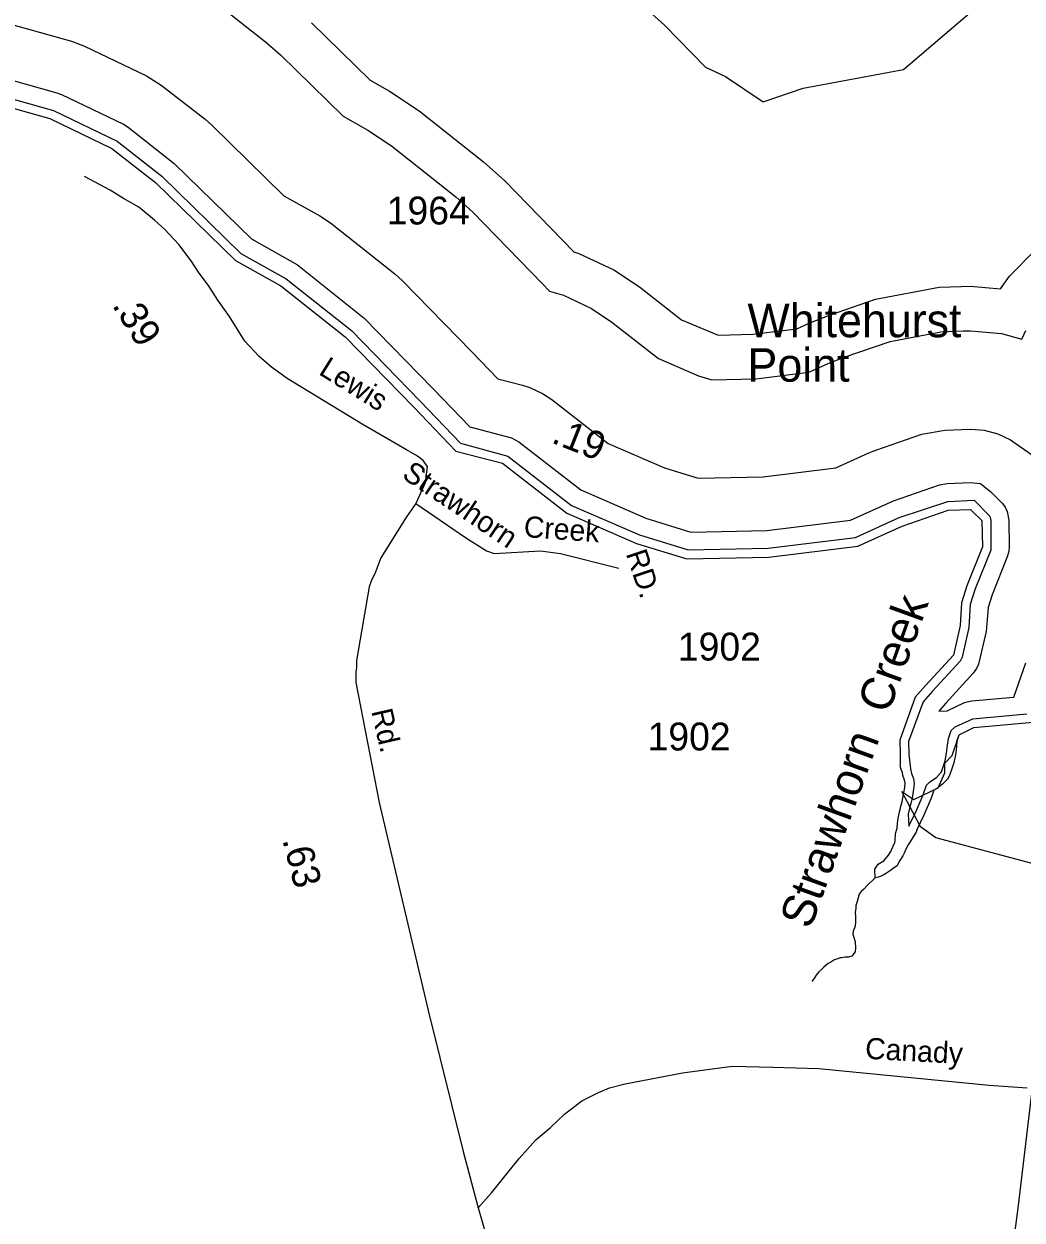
# Model space of a CAD drawing. Extents: x 2532689 to 2764727, y 536648 to 732970.
# Drawn here: x 2695958 to 2700431, y 583950 to 589311 of the extents above; entities that cross this region are included whole.
import ezdxf

# ---------------------------------------------------------------- set-up
doc = ezdxf.new("R2010")
doc.units = 0
for name, color, linetype in [('Exist Boundary Land Use Gamelands State NC Wildlife Resources Commission', 7, 'Continuous'), ('Exist Hydrographic Buffer Line', 7, 'Continuous'), ('Exist Hydrographic Creek Double Shore', 7, 'Continuous'), ('Exist Hydrographic Creek Single Shore', 7, 'Continuous'), ('Exist Hydrographic Creek Single Shore Label', 7, 'Continuous'), ('Exist Hydrographic Point Label', 7, 'Continuous'), ('Exist Hydrographic River Shore', 7, 'Continuous'), ('Exist Road Secondary Mileage Hundredths English Label', 7, 'Continuous'), ('Exist Road Secondary Type 41 Attributed', 7, 'Continuous'), ('Exist Road Secondary Type 51 Attributed', 7, 'Continuous'), ('Exist Road Secondary Type 51 Label', 7, 'Continuous'), ('Exist Road Secondary Type 51 Number Label', 7, 'Continuous')]:
    doc.layers.add(name, color=color, linetype=linetype)

msp = doc.modelspace()

# ---------------------------------------------------------------- linework, layer by layer
at = {"layer": 'Exist Boundary Land Use Gamelands State NC Wildlife Resources Commission'}
for points in [[(2700588.2, 585518), (2700044.4, 585663.1), (2699975.9, 585712.3), (2699941.3, 585777.8), (2699892.3, 585871.1), (2699946.2, 585834.2), (2700054.3, 585887.7), (2700085.2, 585954.7), (2700084.2, 585997.3), (2700117.2, 586031.5), (2700148.2, 586124.7), (2700214.2, 586156.9), (2700480.2, 586180.8)], [(2700290.5, 583072.7), (2700414.8, 584014.9), (2700500.1, 584730.4)]]:
    msp.add_lwpolyline(points, dxfattribs=at)
at = {"layer": 'Exist Hydrographic Buffer Line'}
for points in [[(2698638.4, 589476.4), (2698828.9, 589304.6), (2699012.4, 589116.4), (2699102, 589074.7), (2699270.8, 588961.2), (2699449.2, 589022.6), (2699898.6, 589107), (2700237.2, 589395)], [(2696844.2, 589383.5), (2697040.2, 589230.5), (2697107.3, 589171.9), (2697389, 588896.5), (2697498.9, 588835.1), (2697605.7, 588763.7), (2697893.6, 588535.7), (2697969.7, 588466.9), (2698282.2, 588146.3), (2698313.8, 588113.6), (2698375.5, 588094.3), (2698502, 588035.4), (2698593.1, 587974.1), (2698802, 587811.6), (2698980.6, 587734.2), (2699040.7, 587715.7), (2699238.2, 587720.2), (2699475.6, 587749.2), (2699561.7, 587788.4), (2699633.3, 587816.9), (2699839.2, 587887.6), (2700066.4, 587930.3), (2700166.4, 587934.4), (2700199, 587935), (2700337.9, 587922.9), (2700429.1, 587898.3), (2700447.4, 587937.3)], [(2695894, 589310.4), (2696171, 589232.8), (2696229.4, 589210.8)], [(2697246.9, 589315), (2697509.8, 589058.1), (2697596.5, 589009.8), (2697729.8, 588920.5), (2698017.7, 588692.4), (2698113, 588606.6), (2698422.7, 588288.9), (2698444, 588282.3), (2698601.9, 588208.6), (2698715.9, 588132), (2698904.7, 587985.1), (2699068.8, 587916.4), (2699223.8, 587919.8), (2699420.7, 587944), (2699478.9, 587970.4), (2699568.3, 588006), (2699774.2, 588076.7), (2700058.4, 588130.1), (2700158.4, 588134.2), (2700199, 588135), (2700334.4, 588123.2), (2700374.2, 588180.1), (2700492.3, 588298.9)], [(2696229.4, 589210.8), (2696507.5, 589077.5), (2696573.5, 589036.7), (2696769.5, 588883.6), (2696799.7, 588857.3), (2697123.3, 588540.8), (2697284.4, 588450.9), (2697332.4, 588418.8), (2697620.5, 588190.8), (2697654.8, 588159.8), (2697964.8, 587841.7), (2698082.1, 587719.6), (2698192, 587691.2), (2698225.2, 587680.9), (2698282, 587654.4), (2698323, 587626.8), (2698576, 587430), (2698828.1, 587320.8), (2698979.2, 587274.2), (2699269.9, 587280.7), (2699596.2, 587320.7), (2699744, 587387.9), (2699776, 587400.7), (2699981.9, 587471.5), (2700084.4, 587490.6), (2700199, 587495), (2700261.4, 587489.5), (2700322.3, 587473.3), (2700378.9, 587446.7), (2700488.3, 587370.5)], [(2695829.2, 589079.2), (2696106.2, 589001.7), (2696125.7, 588994.3), (2696403.7, 588861.1), (2696425.7, 588847.5), (2696632, 588685.7), (2696978.5, 588346.9), (2697183.5, 588230.7), (2697482.9, 587992.2), (2697791.5, 587675.6), (2697956, 587504.3), (2698143, 587455.4), (2698175.8, 587437.4), (2698452.8, 587221.9), (2698744.8, 587095.4), (2698945.8, 587033.4), (2699287.2, 587041), (2699662, 587087), (2699853.9, 587173.7), (2700060, 587244.5), (2700094.3, 587250.8), (2700199, 587255), (2700243.8, 587251.1)], [(2695807.6, 589002.2), (2696091.2, 588922.2), (2696376.5, 588784.4), (2696576, 588628.5), (2696930.3, 588282.2), (2697133.7, 588168), (2697425.7, 587936.5), (2697733.7, 587620.3), (2697913.9, 587432.4), (2698126.6, 587374.2)], [(2698126.6, 587374.2), (2698411.4, 587152.5), (2698716.9, 587020.2), (2698934.5, 586953.2), (2699292.9, 586961.1), (2699683.9, 587009.1), (2699880, 587098), (2700097.5, 587170.9), (2700215.5, 587175.7)], [(2700243.8, 587251.1), (2700290.7, 587213.3), (2700343, 587161.6), (2700354.9, 587144.5), (2700363.7, 587125.6), (2700370.9, 587086.6), (2700372.9, 586966.5), (2700371.3, 586945.6), (2700364.3, 586921.6), (2700296, 586752.3), (2700278, 586694.6), (2700270, 586587.8), (2700235.7, 586440.7), (2700226.9, 586421.7), (2700211.8, 586401), (2700088.9, 586265.9), (2700056.9, 586230.9), (2700095.7, 586232.6), (2700173.2, 586269.6)], [(2700215.5, 587175.7), (2700285.8, 587104.5), (2700290.9, 587085.2), (2700289.9, 586951.5), (2700220.8, 586779.3), (2700198.6, 586709.1), (2700192.1, 586605.5), (2700161.9, 586472.9), (2700152.5, 586454.8), (2700029.7, 586319.8), (2699987.2, 586273.1), (2699922.4, 586094.3), (2699923.7, 586038.2), (2699931.4, 585972.5), (2699935.3, 585951.1), (2699943.7, 585928.6), (2699946.4, 585905.8), (2699944.8, 585881.9), (2699937.4, 585841.4), (2699932.7, 585816.8), (2699926.7, 585795.6), (2699919.6, 585768.9), (2699923.7, 585715.2), (2699956.1, 585782), (2699987, 585856.4), (2700001.8, 585898.9), (2700017.8, 585914.1), (2700047.3, 585933.5), (2700069.4, 585958.8), (2700085.4, 586008.6), (2700092, 586042.3), (2700096.5, 586077.6), (2700100.4, 586108.5), (2700113.5, 586144.7), (2700130.8, 586160.6), (2700210.7, 586196.7), (2700451.3, 586218.3)], [(2700173.2, 586269.6), (2700203.5, 586276.4), (2700393.2, 586293.4), (2700447.6, 586447.9)]]:
    msp.add_lwpolyline(points, dxfattribs=at)
at = {"layer": 'Exist Hydrographic Creek Double Shore'}
for p, q in [((2699883.7, 586037.5), (2699884.7, 585985.7)), ((2700036.4, 585878.9), (2700054.5, 585888.5))]:
    msp.add_line(p, q, dxfattribs=at)
for points in [[(2700207, 587127.3), (2700250.9, 587084.5), (2700253, 586966.5), (2700183, 586792.8), (2700159.1, 586716.4), (2700152.9, 586614.3), (2700123, 586481.8), (2700000.1, 586346.7)], [(2700138.5, 586095.8), (2700148.2, 586124.7), (2700214.2, 586156.9), (2700480.2, 586180.8), (2700504.2, 586247.4), (2700566.3, 586423.9), (2700578.2, 586624.7), (2700634.2, 586719), (2701022.5, 586817.8)], [(2700000.1, 586346.7), (2699952.2, 586294.1), (2699882.2, 586100.8), (2699883.7, 586037.5)], [(2700138.5, 586095.8), (2700136.3, 586073.6), (2700134.7, 586055.5), (2700131.6, 586035.3), (2700124.4, 585999), (2700119.1, 585980.8), (2700106.1, 585942.3), (2700096.7, 585925.9), (2700073.5, 585903.2), (2700054.5, 585888.5)], [(2699901.5, 585864.7), (2699905.2, 585888.2), (2699906.4, 585908.2), (2699904.2, 585922.2), (2699895.6, 585942), (2699894.9, 585956), (2699888.8, 585969.8), (2699886.3, 585979.8), (2699884.7, 585985.7)], [(2699861.5, 585649.1), (2699863.8, 585682.4), (2699871, 585706.7), (2699872.2, 585728.8), (2699875.7, 585749), (2699880.8, 585779.1), (2699884.5, 585789.3), (2699888, 585805.5), (2699893.3, 585823.7), (2699894.9, 585833.8), (2699898.4, 585849.9), (2699901.5, 585864.7)], [(2699959.7, 585697.8), (2699992.5, 585765.6), (2700024.5, 585842.4), (2700036.4, 585878.9)], [(2699959.7, 585697.8), (2699955.4, 585688.8), (2699946.4, 585674.3), (2699933.9, 585651.9), (2699920, 585631.8), (2699909.7, 585613), (2699902.7, 585594.9), (2699896.6, 585583.1), (2699885.9, 585565.7), (2699879.8, 585556.6), (2699870.3, 585538.3), (2699854.8, 585527.8), (2699841, 585517.3), (2699823.6, 585504.7), (2699807.8, 585496.2), (2699799.8, 585491.9), (2699786.1, 585487.5), (2699771.9, 585483.1)], [(2699771.9, 585483.1), (2699770.7, 585523.1), (2699786.1, 585545.7), (2699811.7, 585560.5), (2699832.8, 585585.2), (2699842.2, 585601.6), (2699845.9, 585609.7), (2699860.9, 585642.2), (2699861.5, 585649.1)]]:
    msp.add_lwpolyline(points, dxfattribs=at)
at = {"layer": 'Exist Hydrographic Creek Single Shore'}
msp.add_lwpolyline([(2699771.9, 585483.1), (2699737.1, 585449.9), (2699721.7, 585433.4), (2699710, 585423), (2699700.4, 585410.7), (2699696.7, 585394.5), (2699691.3, 585378.3), (2699686, 585360.1), (2699686.2, 585348.1), (2699682.9, 585327.9), (2699683.5, 585311.9), (2699683.9, 585295.9), (2699684.4, 585285.9), (2699682.9, 585267.8), (2699673.5, 585245.5), (2699672.1, 585231.4), (2699678.8, 585211.5), (2699682.9, 585197.6), (2699683.9, 585169.6), (2699682.5, 585151.5), (2699667.3, 585133), (2699653.2, 585128.6), (2699637.2, 585128.1), (2699623.3, 585125.6), (2699615.5, 585125.4), (2699605.4, 585121), (2699597.4, 585118.7), (2699587.8, 585114.4), (2699574, 585106), (2699562.4, 585099.6), (2699542.7, 585083), (2699533, 585074.6), (2699519.3, 585062.2), (2699507.8, 585047.8), (2699500.2, 585035.6), (2699488.7, 585019.1)], dxfattribs=at)
at = {"layer": 'Exist Hydrographic River Shore'}
msp.add_lwpolyline([(2694807.4, 588700.5), (2694803.1, 588706.8), (2694867.9, 588807.9), (2695547, 588960.1), (2695797, 588963.7), (2696074, 588886.2), (2696352.1, 588752.9), (2696547.9, 588599.9), (2696905.9, 588249.9), (2697108.9, 588136.6), (2697397, 587908.5), (2697705, 587592.5), (2697893, 587396.6), (2698102, 587342.6), (2698390.9, 587117.8), (2698703, 586982.7), (2698928.9, 586913), (2699296, 586921.2), (2699695, 586970.1), (2699892.9, 587060.2), (2700099, 587131), (2700199, 587135), (2700207, 587127.3)], dxfattribs=at)
at = {"layer": 'Exist Road Secondary Type 41 Attributed'}
msp.add_lwpolyline([(2697714.5, 587162), (2697936.3, 587009), (2698031, 586948.7), (2698065.5, 586937.9), (2698272.1, 586948.7), (2698362.6, 586937.9), (2698623.1, 586871.2)], dxfattribs=at)
at = {"layer": 'Exist Road Secondary Type 51 Attributed'}
for points in [[(2697765.5, 587328.2), (2697746.5, 587354.7), (2697721.9, 587373.6), (2697672.7, 587402.1), (2697473.9, 587517.6), (2697137, 587722.2), (2697066.9, 587772.3), (2697012, 587819.7), (2696947.7, 587888.8), (2696879.5, 587998.7), (2696826.5, 588072.6), (2696784.9, 588138.9), (2696743.2, 588193.8), (2696707.3, 588248.7), (2696652.4, 588322.6), (2696589.9, 588388.9), (2696542.6, 588430.5), (2696472.5, 588489.3), (2696404.4, 588528.1), (2696343.8, 588566), (2696230.2, 588626.6)], [(2697765.5, 587328.2), (2697756, 587254.3), (2697714.5, 587162)], [(2697714.5, 587162), (2697672, 587102), (2697557.8, 586918.1), (2697530.8, 586846.5), (2697515.3, 586817.5), (2697505.6, 586788.4), (2697447.6, 586457.5), (2697447.6, 586426.5), (2697445.7, 586405.2), (2697444.7, 586359.7), (2697549.1, 585821.7), (2697769.9, 584888.8), (2697926.5, 584257.5), (2697993.4, 584004.7)], [(2697993.4, 584004.7), (2698053.8, 584071.6), (2698133.3, 584171.9), (2698176.6, 584226.7), (2698251.5, 584310.3), (2698317.7, 584365.1), (2698379.7, 584424.2), (2698457.5, 584484.7), (2698533.1, 584522), (2698582.1, 584542.2), (2698652.4, 584561), (2698908.5, 584609.9), (2699131.6, 584640.4), (2699313.1, 584634.6), (2699520.5, 584628.8), (2700282.6, 584555.3), (2700454, 584542.4)], [(2697993.4, 584004.7), (2698026, 583892.1), (2698061.9, 583802.4), (2698128.8, 583637.7), (2698311.4, 583137.8), (2698563.3, 582365.4), (2698768.2, 581684.4), (2698979.8, 581062)]]:
    msp.add_lwpolyline(points, dxfattribs=at)

# ---------------------------------------------------------------- texts
at = {"layer": 'Exist Hydrographic Creek Single Shore Label'}
msp.add_text('Strawhorn  Creek', height=150, rotation=70.1145, dxfattribs=at).set_placement((2699482.4, 585249.2))
at = {"layer": 'Exist Hydrographic Point Label'}
for s, p in [('Whitehurst', (2699200.2, 587906.5)), ('Point', (2699200.2, 587707.3))]:
    msp.add_text(s, height=150, dxfattribs=at).set_placement(p)
at = {"layer": 'Exist Road Secondary Mileage Hundredths English Label'}
for s, rotation, p in [('.39', 302.1369, (2696351.1, 588049.7)), ('.19', 338.4724, (2698316.6, 587435.7)), ('.63', 284.335, (2697115.7, 585654.4))]:
    msp.add_text(s, height=125, rotation=rotation, dxfattribs=at).set_placement(p)
at = {"layer": 'Exist Road Secondary Type 51 Label'}
for s, rotation, p in [('Lewis', 328.0206, (2697274.5, 587743.1)), ('Strawhorn', 326.2085, (2697647.1, 587278.6)), ('Creek', 355.9931, (2698195.7, 587011.1)), ('RD.', 288.2542, (2698654.5, 586937)), ('Rd.', 282.9419, (2697513.8, 586231)), ('Canady', 356.917, (2699725.7, 584673.2))]:
    msp.add_text(s, height=95, rotation=rotation, dxfattribs=at).set_placement(p)
at = {"layer": 'Exist Road Secondary Type 51 Number Label'}
for s, p in [('1964', (2697583.8, 588411.7)), ('1902', (2698888.4, 586457.6)), ('1902', (2698752.6, 586054.6))]:
    msp.add_text(s, height=125, dxfattribs=at).set_placement(p)

doc.saveas('drawing.dxf')
